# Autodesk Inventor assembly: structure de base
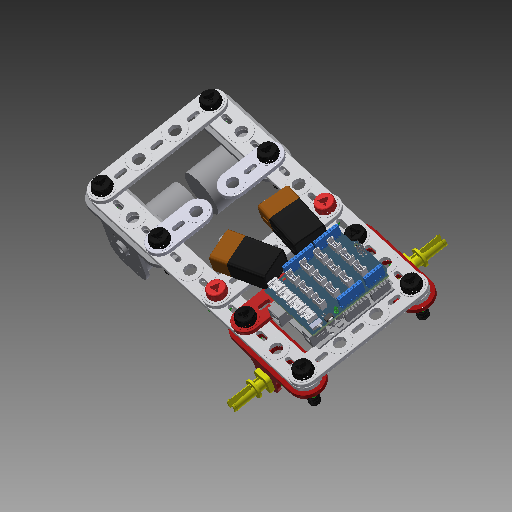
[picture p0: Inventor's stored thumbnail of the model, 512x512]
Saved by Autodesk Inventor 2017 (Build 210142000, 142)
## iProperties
Part Number: structure de base
Material: Générique
Document SubType Name: Assembly
Designer: ficho
Author: ficho
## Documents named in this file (12)
- G:\travail\année 2017-2018\1STI2D\challenge\structure de base.iam
- G:\travail\année 2017-2018\1STI2D\challenge\pièce meccano à 8 trous de base paramétré.ipt
- G:\travail\année 2017-2018\1STI2D\challenge\adaptation moteur.iam
- G:\travail\année 2017-2018\1STI2D\challenge\pièce meccano à 4 trous de base paramétré.ipt
- G:\travail\année 2017-2018\1STI2D\challenge\arduino uno et shield.iam
- G:\travail\année 2017-2018\1STI2D\challenge\pièce meccano à 2 trous de base.ipt
- G:\travail\année 2017-2018\1STI2D\challenge\pièce meccano à 3 trous de base paramétré.ipt
- G:\travail\année 2017-2018\1STI2D\challenge\pièces meccano step\A054.ipt
- G:\travail\année 2017-2018\1STI2D\challenge\pièces meccano step\Nut.ipt
- G:\travail\année 2017-2018\1STI2D\challenge\pièces meccano step\A051 - MECCANO JUNIOR.ipt
- G:\travail\année 2017-2018\1STI2D\challenge\porte roue libre.iam
- G:\travail\année 2017-2018\1STI2D\challenge\pièces electro step\9V-battery.ipt
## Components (35 placed, 11 different names)
1. pièce meccano à 8 trous de base paramétré:1 — Logement:2, Placage:2, Logement:5, Logement:6, Logement:8, Logement:9, Angle:2, Logement:12, Angle:5, Logement:35, Logement:38
2. pièce meccano à 8 trous de base paramétré:2 — Logement:3, Logement:4, Logement:7, Placage:3, Placage:4, Angle:1, Logement:11, Angle:4, Logement:34, Logement:39, Logement:40
3. adaptation moteur:1 [sub-assembly] — Logement:2, Placage:2, Logement:32, Logement:33
4. adaptation moteur:2 [sub-assembly] — Logement:7, Placage:3, Angle:6, Logement:30, Logement:31
5. pièce meccano à 4 trous de base paramétré:1 — Logement:4, Logement:6, Angle:1, Logement:22, Logement:23, Angle:7
6. pièce meccano à 4 trous de base paramétré:2 — Logement:3, Logement:5, Placage:5, Logement:19, Logement:21
7. pièce meccano à 4 trous de base paramétré:3 — Logement:8, Placage:4, Logement:26, Logement:29, Placage:9
8. arduino uno et shield:1 [sub-assembly] — Placage:5, Angle:6
9. pièce meccano à 2 trous de base:1 — Logement:11, Angle:4, Logement:28
10. pièce meccano à 2 trous de base:2 — Logement:12, Angle:5, Logement:27
11. pièce meccano à 3 trous de base paramétré:1 — Logement:9, Angle:2, Logement:36, Placage:7
12. A054:3 — Logement:21
13. A054:5 — Logement:19
14. Nut:1 — Logement:30
15. Nut:2 — Logement:31
16. Nut:3 — Logement:32
17. Nut:4 — Logement:33
18. Nut:5 — Logement:35
19. Nut:6 — Logement:34
20. Nut:9 — Logement:43
21. Nut:10 — Logement:42
22. A051 - MECCANO JUNIOR:1 — Logement:26
23. A051 - MECCANO JUNIOR:2 — Logement:29
24. A054:6 — Logement:27
25. A054:7 — Logement:28
26. A054:8 — Logement:22
27. A054:9 — Logement:23
28. A054:11 — Logement:36, Placage:8
29. porte roue libre:1 [sub-assembly] — Logement:38, Placage:8, Logement:43, Logement:44
30. porte roue libre:2 [sub-assembly] — Logement:39, Angle:7, Logement:41, Logement:42
31. 9V-battery:1 — Placage:7
32. A054:12 — Logement:40
33. Nut:11 — Logement:44
34. Nut:12 — Logement:41
35. 9V-battery:2 — Placage:9
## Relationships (45: Insert 32, Mate 7, Angle 6)
- Logement:2 [Insert]: pièce meccano à 8 trous de base paramétré:1 ↔ adaptation moteur:1
- Placage:2 [Mate]: pièce meccano à 8 trous de base paramétré:1 ↔ adaptation moteur:1
- Logement:3 [Insert]: pièce meccano à 8 trous de base paramétré:2 ↔ pièce meccano à 4 trous de base paramétré:2
- Logement:4 [Insert]: pièce meccano à 8 trous de base paramétré:2 ↔ pièce meccano à 4 trous de base paramétré:1
- Logement:5 [Insert]: pièce meccano à 8 trous de base paramétré:1 ↔ pièce meccano à 4 trous de base paramétré:2
- Logement:6 [Insert]: pièce meccano à 8 trous de base paramétré:1 ↔ pièce meccano à 4 trous de base paramétré:1
- Logement:7 [Insert]: pièce meccano à 8 trous de base paramétré:2 ↔ adaptation moteur:2
- Placage:3 [Mate]: pièce meccano à 8 trous de base paramétré:2 ↔ adaptation moteur:2
- Logement:8 [Insert]: pièce meccano à 8 trous de base paramétré:1 ↔ pièce meccano à 4 trous de base paramétré:3
- Placage:4 [Mate]: pièce meccano à 8 trous de base paramétré:2 ↔ pièce meccano à 4 trous de base paramétré:3
- Logement:9 [Insert]: pièce meccano à 8 trous de base paramétré:1 ↔ pièce meccano à 3 trous de base paramétré:1
- Angle:1: pièce meccano à 8 trous de base paramétré:2 ↔ pièce meccano à 4 trous de base paramétré:1
- Angle:2: pièce meccano à 8 trous de base paramétré:1 ↔ pièce meccano à 3 trous de base paramétré:1
- Logement:11 [Insert]: pièce meccano à 8 trous de base paramétré:2 ↔ pièce meccano à 2 trous de base:1
- Logement:12 [Insert]: pièce meccano à 8 trous de base paramétré:1 ↔ pièce meccano à 2 trous de base:2
- Angle:4: pièce meccano à 8 trous de base paramétré:2 ↔ pièce meccano à 2 trous de base:1
- Angle:5: pièce meccano à 8 trous de base paramétré:1 ↔ pièce meccano à 2 trous de base:2
- Placage:5 [Mate]: pièce meccano à 4 trous de base paramétré:2 ↔ arduino uno et shield:1
- Angle:6: adaptation moteur:2 ↔ arduino uno et shield:1
- Logement:19 [Insert]: pièce meccano à 4 trous de base paramétré:2 ↔ A054:5
- Logement:21 [Insert]: pièce meccano à 4 trous de base paramétré:2 ↔ A054:3
- Logement:22 [Insert]: pièce meccano à 4 trous de base paramétré:1 ↔ A054:8
- Logement:23 [Insert]: pièce meccano à 4 trous de base paramétré:1 ↔ A054:9
- Logement:26 [Insert]: pièce meccano à 4 trous de base paramétré:3 ↔ A051 - MECCANO JUNIOR:1
- Logement:27 [Insert]: pièce meccano à 2 trous de base:2 ↔ A054:6
- Logement:28 [Insert]: pièce meccano à 2 trous de base:1 ↔ A054:7
- Logement:29 [Insert]: pièce meccano à 4 trous de base paramétré:3 ↔ A051 - MECCANO JUNIOR:2
- Logement:30 [Insert]: adaptation moteur:2 ↔ Nut:1
- Logement:31 [Insert]: adaptation moteur:2 ↔ Nut:2
- Logement:32 [Insert]: adaptation moteur:1 ↔ Nut:3
- Logement:33 [Insert]: adaptation moteur:1 ↔ Nut:4
- Logement:34 [Insert]: pièce meccano à 8 trous de base paramétré:2 ↔ Nut:6
- Logement:35 [Insert]: pièce meccano à 8 trous de base paramétré:1 ↔ Nut:5
- Logement:36 [Insert]: pièce meccano à 3 trous de base paramétré:1 ↔ A054:11
- Placage:7 [Mate]: pièce meccano à 3 trous de base paramétré:1 ↔ 9V-battery:1
- Logement:38 [Insert]: pièce meccano à 8 trous de base paramétré:1 ↔ porte roue libre:1
- Placage:8 [Mate]: A054:11 ↔ porte roue libre:1
- Logement:39 [Insert]: pièce meccano à 8 trous de base paramétré:2 ↔ porte roue libre:2
- Logement:40 [Insert]: pièce meccano à 8 trous de base paramétré:2 ↔ A054:12
- Angle:7: pièce meccano à 4 trous de base paramétré:1 ↔ porte roue libre:2
- Logement:41 [Insert]: porte roue libre:2 ↔ Nut:12
- Logement:42 [Insert]: Nut:10 ↔ porte roue libre:2
- Logement:43 [Insert]: Nut:9 ↔ porte roue libre:1
- Logement:44 [Insert]: porte roue libre:1 ↔ Nut:11
- Placage:9 [Mate]: pièce meccano à 4 trous de base paramétré:3 ↔ 9V-battery:2
